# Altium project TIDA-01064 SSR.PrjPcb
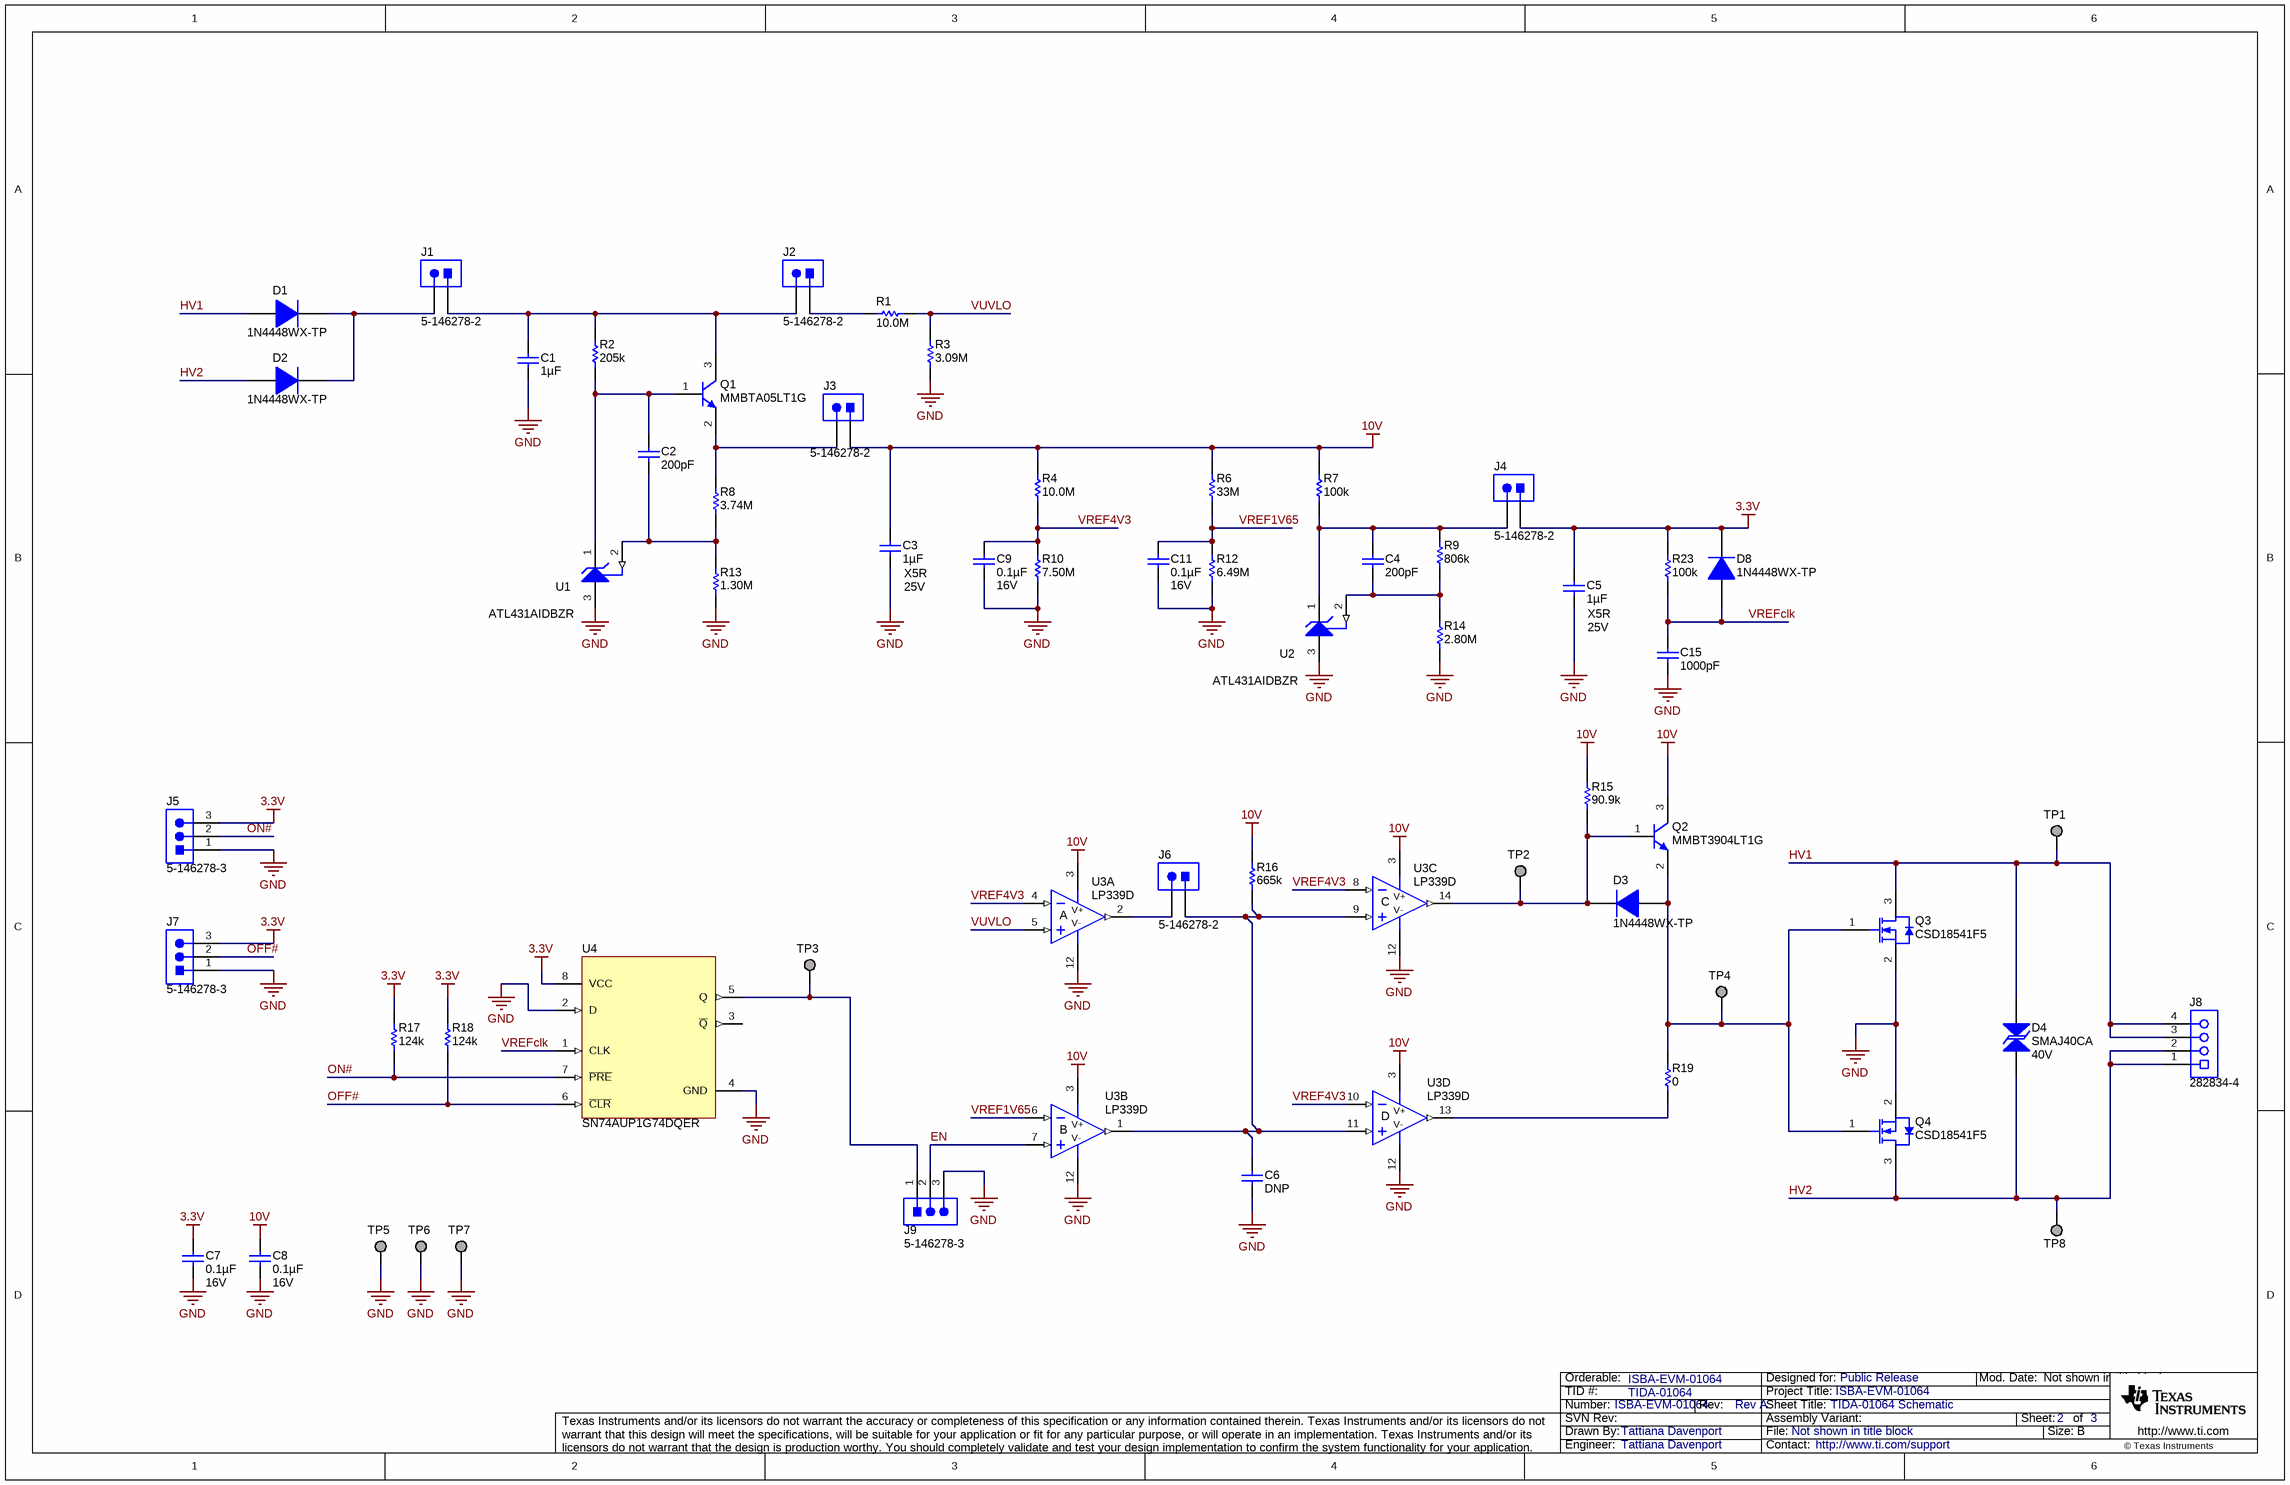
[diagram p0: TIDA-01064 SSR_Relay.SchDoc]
EVM_Orderable: ISBA-EVM-01064; PCB_Layout: Tattiana Davenport; PCB_Rev: Rev A; PRJ_Customer: Public Release; PRJ_Engineer: Tattiana Davenport; PRJ_Number: ISBA-EVM-01064; PRJ_Title: ISBA-EVM-01064; SCH_Rev: Rev A; TechSupport: http://www.ti.com/support; TID: TIDA-01064
3 sheets, 83 parts. Net scope: global (net labels, ports and power ports of the same name join across sheets).
Board file: TIDA-01064 SSR.PcbDoc
Sheets:
  TIDA-01064 SSR_Relay.SchDoc
  TIDA-01064 SSR_TID_Hardware.SchDoc
  TIDA-01064 SSR_CoverSheet.SchDoc

## Sheet TIDA-01064 SSR_Relay.SchDoc: TIDA-01064 Schematic
size 431 x 279 mm; Date: Not shown in title block; ApprovedBy: Not shown in title block; CheckedBy: Not shown in title block; Author: Not shown in title block; CompanyName: Not shown in title block; DrawnBy: Tattiana Davenport; Engineer: Not shown in title block; Organization: Not shown in title block; Address1: Not shown in title block; Address2: Not shown in title block; Address3: Not shown in title block; Address4: Not shown in title block; DocumentNumber: 1; Revision: Use project parameter SCH_Rev; SheetNumber: 2; SheetTotal: 3; PageSetup: Record=PageOptions¦CenterHorizontal=True¦CenterVertical=True¦PrintScale=0.62¦XCorrection=1.00¦YCorrection=1.00¦PrintKind=0¦BorderSize=5000000¦LeftOffset=0¦BottomOffset=0¦Orientation=2¦PaperLength=1000¦PaperWidth=1000¦Scale=100¦PaperSource=15¦PrintQuality=-3¦MediaType=1¦DitherType=10¦PrintScaleMode=1¦PaperKind=Letter¦PaperIndex=1

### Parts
C1  ValueDisplayed: 1µF  [1206_180]  (hidden comment: CL31B105KCHNNNE)
C2  ValueDisplayed: 200pF  [0603]  (hidden comment: GRM1885C1H201JA01D)
C3  ValueDisplayed: 1µF  Value2: 25V  TempCo: X5R  [0603]  (hidden comment: GRM188R61E105KA12D)
C4  ValueDisplayed: 200pF  [0603]  (hidden comment: GRM1885C1H201JA01D)
C5  ValueDisplayed: 1µF  Value2: 25V  TempCo: X5R  [0603]  (hidden comment: GRM188R61E105KA12D)
C6  ValueDisplayed: DNP  [0603]  (hidden comment: GRM188R61E105KA12D)
C7  ValueDisplayed: 0.1µF  Value2: 16V  [0603]  (hidden comment: GRM188R71C104KA01D)
C8  ValueDisplayed: 0.1µF  Value2: 16V  [0603]  (hidden comment: GRM188R71C104KA01D)
C9  ValueDisplayed: 0.1µF  Value2: 16V  [0603]  (hidden comment: GRM188R71C104KA01D)
C11  ValueDisplayed: 0.1µF  Value2: 16V  [0603]  (hidden comment: GRM188R71C104KA01D)
C15  ValueDisplayed: 1000pF  [0603]  (hidden comment: GRM188R71E102KA01D)
D1  1N4448WX-TP  [sod-323]
D2  1N4448WX-TP  [sod-323]
D3  1N4448WX-TP  [sod-323]
D4  SMAJ40CA  value 40V  [SMA]
D8  1N4448WX-TP  [sod-323]
J1  5-146278-2  [TE_5-146278-2]
J2  5-146278-2  [TE_5-146278-2]
J3  5-146278-2  [TE_5-146278-2]
J4  5-146278-2  [TE_5-146278-2]
J5  5-146278-3  [TE_5-146278-3]
J6  5-146278-2  [TE_5-146278-2]
J7  5-146278-3  [TE_5-146278-3]
J8  282834-4  [TEC_282834-4]
J9  5-146278-3  [TE_5-146278-3]
Q1  MMBTA05LT1G  [SOT-23]
Q2  MMBT3904LT1G  [SOT-23]
Q3  CSD18541F5  [YJK0003A]
Q4  CSD18541F5  [YJK0003A]
R1  ValueDisplayed: 10.0M  [0805_HV]  (hidden comment: CRCW080510M0FKEA)
R2  ValueDisplayed: 205k  [0805_HV]  (hidden comment: CRCW0805205KFKEA)
R3  ValueDisplayed: 3.09M  [0805_HV]  (hidden comment: CRCW08053M09FKEA)
R4  ValueDisplayed: 10.0M  [0805_HV]  (hidden comment: CRCW080510M0FKEA)
R6  ValueDisplayed: 33M  [0805_HV]  (hidden comment: RC0805JR-0733ML)
R7  ValueDisplayed: 100k  [0805_HV]  (hidden comment: CRCW0805100KFKEA)
R8  ValueDisplayed: 3.74M  [0805_HV]  (hidden comment: CRCW08053M74FKEA)
R9  ValueDisplayed: 806k  [0805_HV]  (hidden comment: CRCW0805806KFKEA)
R10  ValueDisplayed: 7.50M  [0805_HV]  (hidden comment: CRCW08057M50FKEA)
R12  ValueDisplayed: 6.49M  [0805_HV]  (hidden comment: CRCW08056M49FKEA)
R13  ValueDisplayed: 1.30M  [0805_HV]  (hidden comment: CRCW08051M30FKEA)
R14  ValueDisplayed: 2.80M  [0805_HV]  (hidden comment: CRCW08052M80FKEA)
R15  ValueDisplayed: 90.9k  [0805_HV]  (hidden comment: CRCW080590K9FKEA)
R16  ValueDisplayed: 665k  [0805_HV]  (hidden comment: CRCW0805665KFKEA)
R17  ValueDisplayed: 124k  [0805_HV]  (hidden comment: CRCW0805124KFKEA)
R18  ValueDisplayed: 124k  [0805_HV]  (hidden comment: CRCW0805124KFKEA)
R19  ValueDisplayed: 0  [0805_HV]  (hidden comment: CRCW08050000Z0EA)
R23  ValueDisplayed: 100k  [0805_HV]  (hidden comment: CRCW0805100KFKEA)
TP1  TESTPOINT  [Keystone_5019]  (value not drawn)  (no BOM)
TP2  TESTPOINT  [Keystone_5019]  (value not drawn)  (no BOM)
TP3  TESTPOINT  [Keystone_5019]  (value not drawn)  (no BOM)
TP4  TESTPOINT  [Keystone_5019]  (value not drawn)  (no BOM)
TP5  TESTPOINT  [Keystone_5019]  (value not drawn)  (no BOM)
TP6  TESTPOINT  [Keystone_5019]  (value not drawn)  (no BOM)
TP7  TESTPOINT  [Keystone_5019]  (value not drawn)  (no BOM)
TP8  TESTPOINT  [Keystone_5019]  (value not drawn)  (no BOM)
U1  ATL431AIDBZR  [DBZ0003A_M]
U2  ATL431AIDBZR  [DBZ0003A_M]
U3  LP339D  [D0014A_N]  (parts A,B,C,D of 4)
U4  SN74AUP1G74DQER  [DQE0008A]

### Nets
3.3V: C5.1 C7.2 D8.1(K) J4.1 J5.3 J7.3 R17.2 R18.2 R23.1 U4.8(VCC)
10V: C3.1 C8.2 J3.1 Q2.3(C) R4.2 R6.2 R7.2 R15.2 R16.2 U3.3(V+)
GND: C1.2 C3.2 C5.2 C6.2 C7.1 C8.1 C9.1 C11.1 C15.2 J5.1 J7.1 J9.3 Q3.2(S) Q4.2(S) R3.1 R10.1 R12.1 R13.1 R14.1 TP5.1 TP6.1 TP7.1 U1.3(ANODE) U2.3(ANODE) U3.12(V-) U4.2(D) U4.4(GND)
EN: J9.2 U3.7(+IN2)
HV1: D1.2(A) D4.2 J8.3 J8.4 Q3.3(D) TP1.1
HV2: D2.2(A) D4.1 J8.1 J8.2 Q4.3(D) TP8.1
OFF#: J7.2 R18.1 U4.6(~{CLR})
ON#: J5.2 R17.1 U4.7(~{PRE})
VREF1V65: C11.2 R6.1 R12.2 U3.6(-IN2)
VREF4V3: C9.2 R4.1 R10.2 U3.4(-IN1) U3.8(-IN3) U3.10(-IN4)
VREFclk: C15.1 D8.2(A) R23.2 U4.1(CLK)
VUVLO: R1.2 R3.2 U3.5(+IN1)
NetC1_1: C1.1 J1.1 J2.2 Q1.3(C) R2.2
NetC2_1: C2.1 Q1.1(B) R2.1 U1.1(CATHODE)
NetC2_2: C2.2 R8.1 R13.2 U1.2(REF)
NetC4_1: C4.1 J4.2 R7.1 R9.2 U2.1(CATHODE)
NetC4_2: C4.2 R9.1 R14.2 U2.2(REF)
NetC6_1: C6.1 J6.1 R16.1 U3.1(OUT2) U3.9(+IN3) U3.11(+IN4)
NetD1_1: D1.1(K) D2.1(K) J1.2
NetD3_1: D3.1(K) Q2.1(B) R15.1 TP2.1 U3.14(OUT3)
NetD3_2: D3.2(A) Q2.2(E) Q3.1(G) Q4.1(G) R19.2 TP4.1
NetJ2_1: J2.1 R1.1
NetJ3_2: J3.2 Q1.2(E) R8.2
NetJ6_2: J6.2 U3.2(OUT1)
NetJ9_1: J9.1 TP3.1 U4.5(Q)
NetR19_1: R19.1 U3.13(OUT4)

Not connected (* = marked no-connect by the designer): U4 3(~{Q})

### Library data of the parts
C1 = CL31B105KCHNNNE: CAP, CERM, 1 µF, 100 V, +/- 10%, X7R, 1206; Manufacturer: Samsung; Polarized: N; CompType: Capacitor; Value: 1uF; U/M: EA; Cap_F: 0.000001; Tolerance_%: 10; Value1: Unknown; VDC_V: 100; Value2: 100V; TaMin_C: -55; TaMax_C: 125; Cap_Case: 1206; AEC Category: Q200; SizeArea_mm2: 5.12; SizeAreaWB_mm2: 10.92; SizeX_mm: 3.2; SizeY_mm: 1.6; SizeZ_mm: 1.8
C2 C4 = GRM1885C1H201JA01D: CAP, CERM, 200 pF, 50 V, +/- 5%, C0G/NP0, 0603; Manufacturer: MuRata; Polarized: N; CompType: Capacitor; Value: 200pF; U/M: EA; Cap_F: 0.0000000002; Tolerance_%: 5; Value1: Unknown; VDC_V: 50; Value2: 50V; TaMin_C: -55; TaMax_C: 125; AEC Category: Q200
C3 C5 = GRM188R61E105KA12D: CAP, CERM, 1 µF, 25 V, +/- 10%, X5R, 0603; Manufacturer: MuRata; Polarized: N; CompType: Capacitor; Value: 1uF; U/M: EA; Cap_F: 0.000001; Tolerance_%: 10; Value1: Unknown; VDC_V: 25; TaMin_C: -55; TaMax_C: 85; AEC Category: Q200
C6 = GRM188R61E105KA12D: CAP, CERM, 1 µF, 25 V, +/- 10%, X5R, 0603; Manufacturer: MuRata; Polarized: N; CompType: Capacitor; Value: 1uF; U/M: EA; Cap_F: 0.000001; Tolerance_%: 10; Value1: Unknown; VDC_V: 25; Value2: 25V; TaMin_C: -55; TaMax_C: 85; AEC Category: Q200
C7-C9 C11 = GRM188R71C104KA01D: CAP, CERM, 0.1 µF, 16 V, +/- 10%, X7R, 0603; Manufacturer: MuRata; Polarized: N; CompType: Capacitor; Value: 0.1uF; U/M: EA; Cap_F: 0.0000001; Tolerance_%: 10; Value1: Unknown; VDC_V: 16; TaMin_C: -55; TaMax_C: 125; AEC Category: Q200
C15 = GRM188R71E102KA01D: CAP, CERM, 1000 pF, 25 V, +/- 10%, X7R, 0603; Manufacturer: MuRata; Polarized: N; CompType: Capacitor; Value: 1000pF; U/M: EA; Cap_F: 0.000000001; Tolerance_%: 10; Value1: Unknown; VDC_V: 25; Value2: 25V; TaMin_C: -55; TaMax_C: 125; SizeArea_mm2: 1.28; SizeAreaWB_mm2: 4.68; SizeX_mm: 1.6; SizeY_mm: 0.8; SizeZ_mm: 1; AEC Category: Q200
D1-D3 D8 = 1N4448WX-TP: Diode, Switching, 75 V, 0.25 A, SOD-323; Manufacturer: Micro Commercial Components; U/M: EA; Value: 75V; Value1: 0.25A; Io_A: 0.25; Vr_V: 75; TJmax_C: 150; AEC Category: Q101
D4 = SMAJ40CA: Diode, TVS, Bi, 40 V, 400 W, SMA; Manufacturer: Littelfuse; U/M: EA; Power_W: 400; Vr_V: 40; Value1: 400W; RJA_CperW: 120; AEC Category: Q101
J1-J4 J6 = 5-146278-2: Header, 100mil, 2x1, Tin, TH; Manufacturer: TE Connectivity; SymbolCreator: a0412235; U/M: EA
J5 J7 J9 = 5-146278-3: Header, 100mil, 3x1, Tin, TH; Manufacturer: TE Connectivity; SymbolCreator: a0799628
J8 = 282834-4: Terminal Block, 100mil, 4X1 TH; Manufacturer: TE Connectivity; SymbolCreator: a0411947
Q1 = MMBTA05LT1G, ON Semiconductor: Transistor, NPN, 60 V, 0.5 A, AEC-Q101, SOT-23; CompType: BJT; PNP: 0; NPN: 1; Vceo_V: 60; Vcesat1_V: 0.25; Value: 60 V; IcRated_A: 0.5; Value1: 0.5 A; TaMin_C: -55; TaMax_C: 150; U/M: EA; AEC Category: Q101; AEC Qualified: Y
Q2 = MMBT3904LT1G, ON Semiconductor: Transistor, NPN, 40 V, 0.2 A, SOT-23; CompType: BJT; PNP: 0; NPN: 1; Vceo_V: 40; Vcesat1_V: 0.3; Value: 40 V; IcRated_A: 0.2; Value1: 0.2 A; HfeMax: 300; TaMin_C: -55; TaMax_C: 150; U/M: EA; AEC Category: Q101
Q3 Q4 = CSD18541F5: MOSFET, N-CH, 60 V,  A, PICOSTAR-3; Manufacturer: Texas Instruments; Alternate Manufacturer: None; U/M: EA; ChType: N; Value: 60V; VdsMax_V: 60; Value1: 0.13 ohm; Rdson45_ohm: 0.13; Value2: 9.2 nC; QgTyp_nC: 9.2; Vgs_V: 20; AEC Category: Q101
R1 R4 = CRCW080510M0FKEA: RES, 10.0 M, 1%, 0.125 W, 0805; Manufacturer: Vishay-Dale; CompType: Resistor; Value: 10.0Meg; Res_ohm: 10000000; Value_Code: 10M0; Tolerance_%: 1; Power_W: 0.125; Value2: 0.125W; VDC_V: 150; TempCo: 100 ppm/C; EIA_Code: E96; U/M: EA; AEC Category: Q200
R2 = CRCW0805205KFKEA: RES, 205 k, 1%, 0.125 W, 0805; Manufacturer: Vishay-Dale; CompType: Resistor; Value: 205k; Res_ohm: 205000; Tolerance_%: 1; Power_W: 0.125; Value2: 0.125W; VDC_V: 150; TempCo: 100 ppm/C; EIA_Code: E96; U/M: EA; AEC Category: Q200
R3 = CRCW08053M09FKEA: RES, 3.09 M, 1%, 0.125 W, 0805; Manufacturer: Vishay-Dale; CompType: Resistor; Value: 3.09Meg; Res_ohm: 3090000; Value_Code: 3M09; Tolerance_%: 1; Power_W: 0.125; Value2: 0.125W; VDC_V: 150; TempCo: 100 ppm/C; EIA_Code: E96; U/M: EA; AEC Category: Q200
R6 = RC0805JR-0733ML: RES, 33 M, 5%, 0.125 W, 0805; Manufacturer: Yageo America; CompType: Resistor; Value: 33Meg; Res_ohm: 33000000; Value_Code: 33M0; Tolerance_%: 5; Power_W: 0.125; Value2: 0.125W; VDC_V: 150; TempCo: 300 ppm/C; U/M: EA; AEC Category: Q200; AEC Qualified: N
R7 R23 = CRCW0805100KFKEA: RES, 100 k, 1%, 0.125 W, 0805; Manufacturer: Vishay-Dale; CompType: Resistor; Value: 100k; Res_ohm: 100000; Tolerance_%: 1; Power_W: 0.125; Value2: 0.125W; VDC_V: 150; TempCo: 100 ppm/C; EIA_Code: E96; U/M: EA; AEC Category: Q200
R8 = CRCW08053M74FKEA: RES, 3.74 M, 1%, 0.125 W, 0805; Manufacturer: Vishay-Dale; CompType: Resistor; Value: 3.74Meg; Res_ohm: 3740000; Value_Code: 3M74; Tolerance_%: 1; Power_W: 0.125; Value2: 0.125W; VDC_V: 150; TempCo: 100 ppm/C; EIA_Code: E96; U/M: EA; AEC Category: Q200
R9 = CRCW0805806KFKEA: RES, 806 k, 1%, 0.125 W, 0805; Manufacturer: Vishay-Dale; CompType: Resistor; Value: 806k; Res_ohm: 806000; Tolerance_%: 1; Power_W: 0.125; Value2: 0.125W; VDC_V: 150; TempCo: 100 ppm/C; EIA_Code: E96; U/M: EA; AEC Category: Q200
R10 = CRCW08057M50FKEA: RES, 7.50 M, 1%, 0.125 W, 0805; Manufacturer: Vishay-Dale; CompType: Resistor; Value: 7.50Meg; Res_ohm: 7500000; Value_Code: 7M50; Tolerance_%: 1; Power_W: 0.125; Value2: 0.125W; VDC_V: 150; TempCo: 100 ppm/C; EIA_Code: E96; U/M: EA; AEC Category: Q200
R12 = CRCW08056M49FKEA: RES, 6.49 M, 1%, 0.125 W, 0805; Manufacturer: Vishay-Dale; CompType: Resistor; Value: 6.49Meg; Res_ohm: 6490000; Value_Code: 6M49; Tolerance_%: 1; Power_W: 0.125; Value2: 0.125W; VDC_V: 150; TempCo: 100 ppm/C; EIA_Code: E96; U/M: EA; AEC Category: Q200
R13 = CRCW08051M30FKEA: RES, 1.30 M, 1%, 0.125 W, 0805; Manufacturer: Vishay-Dale; CompType: Resistor; Value: 1.30Meg; Res_ohm: 1300000; Value_Code: 1M30; Tolerance_%: 1; Power_W: 0.125; Value2: 0.125W; VDC_V: 150; TempCo: 100 ppm/C; EIA_Code: E96; U/M: EA; AEC Category: Q200
R14 = CRCW08052M80FKEA: RES, 2.80 M, 1%, 0.125 W, 0805; Manufacturer: Vishay-Dale; CompType: Resistor; Value: 2.80Meg; Res_ohm: 2800000; Value_Code: 2M80; Tolerance_%: 1; Power_W: 0.125; Value2: 0.125W; VDC_V: 150; TempCo: 100 ppm/C; EIA_Code: E96; U/M: EA; AEC Category: Q200
R15 = CRCW080590K9FKEA: RES, 90.9 k, 1%, 0.125 W, 0805; Manufacturer: Vishay-Dale; CompType: Resistor; Value: 90.9k; Res_ohm: 90900; Value_Code: 90k9; Tolerance_%: 1; Power_W: 0.125; Value2: 0.125W; VDC_V: 150; TempCo: 100 ppm/C; EIA_Code: E96; U/M: EA; AEC Category: Q200
R16 = CRCW0805665KFKEA: RES, 665 k, 1%, 0.125 W, 0805; Manufacturer: Vishay-Dale; CompType: Resistor; Value: 665k; Res_ohm: 665000; Tolerance_%: 1; Power_W: 0.125; Value2: 0.125W; VDC_V: 150; TempCo: 100 ppm/C; EIA_Code: E96; U/M: EA; AEC Category: Q200; SizeArea_mm2: 2.5; SizeX_mm: 2; SizeY_mm: 1.25; SizeZ_mm: 1.45
R17 R18 = CRCW0805124KFKEA: RES, 124 k, 1%, 0.125 W, 0805; Manufacturer: Vishay-Dale; CompType: Resistor; Value: 124k; Res_ohm: 124000; Tolerance_%: 1; Power_W: 0.125; Value2: 0.125W; VDC_V: 150; TempCo: 100 ppm/C; EIA_Code: E96; U/M: EA; AEC Category: Q200
R19 = CRCW08050000Z0EA: RES, 0, 5%, 0.125 W, 0805; Manufacturer: Vishay-Dale; CompType: Resistor; Value: 0; Value_Code: 0000; Tolerance_%: 5; Power_W: 0.125; Value2: 0.125W; VDC_V: 150; TempCo: 200 ppm/C; EIA_Code: E24; U/M: EA; AEC Category: Q200
TP1-TP8 = 5019: Test Point, Miniature, SMT; Manufacturer: Keystone; CompType: Test Point Loop
U1 U2 = ATL431AIDBZR: 2.5V Low Iq Adjustable Precision Shunt Regulator, DBZ0003A; Manufacturer: Texas Instruments; SymbolCreator: a0412235; CompType: IC; U/M: EA
U3 = LP339D: Quad, Low-Power, General Purpose Differential Comparator, D0014A; Manufacturer: Texas Instruments; SymbolCreator: Altium; CompType: OpAmp IC
U4 = SN74AUP1G74DQER: LOW-POWER SINGLE POSITIVE-EDGE-TRIGGERED D-TYPE FLIP-FLOP WITH CLEAR AND PRESET, DQE0008A; Manufacturer: Texas Instruments; SymbolCreator: a0799628; CompType: IC; U/M: EA

## Sheet TIDA-01064 SSR_TID_Hardware.SchDoc: Hardware
size 431 x 279 mm; Date: Not shown in title block; ApprovedBy: Not shown in title block; CheckedBy: Not shown in title block; Author: Not shown in title block; CompanyName: Not shown in title block; DrawnBy: Tattiana Davenport; Engineer: Not shown in title block; Organization: Not shown in title block; Address1: Not shown in title block; Address2: Not shown in title block; Address3: Not shown in title block; Address4: Not shown in title block; DocumentNumber: 1; Revision: Use project parameter SCH_Rev; SheetNumber: 3; SheetTotal: 3; PageSetup: Record=PageOptions¦CenterHorizontal=True¦CenterVertical=True¦PrintScale=1.00¦XCorrection=1.00¦YCorrection=1.00¦PrintKind=0¦BorderSize=5000000¦LeftOffset=0¦BottomOffset=0¦Orientation=2¦PaperLength=1000¦PaperWidth=1000¦Scale=100¦PaperSource=15¦PrintQuality=600¦MediaType=1¦DitherType=10¦PaperKind=Letter¦PrintScaleMode=1
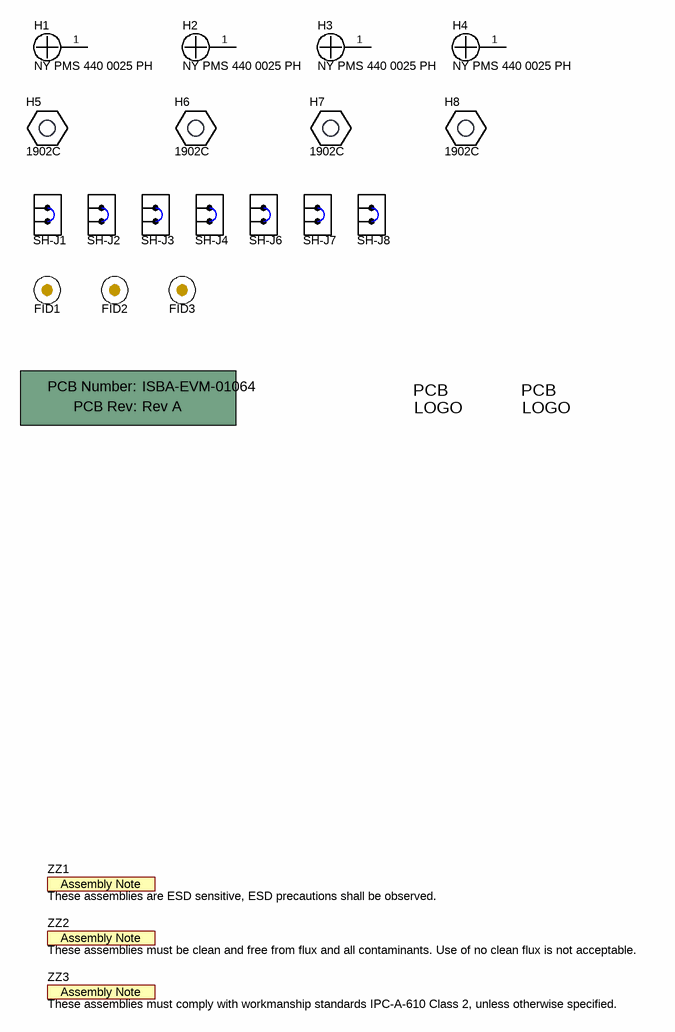
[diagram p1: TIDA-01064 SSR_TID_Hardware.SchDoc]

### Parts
!PCB1  Printed Circuit Board  (value not drawn)  (mechanical)
FCC_Disclaimer  FCC disclaimer  [FCC_disclaimer]  (value not drawn)  (no BOM)
FID1  Fiducial  [Fiducial10-20]  (value not drawn)
FID2  Fiducial  [Fiducial10-20]  (value not drawn)
FID3  Fiducial  [Fiducial10-20]  (value not drawn)
H1  NY PMS 440 0025 PH  [NY PMS 440 0025 PH]
H2  NY PMS 440 0025 PH  [NY PMS 440 0025 PH]
H3  NY PMS 440 0025 PH  [NY PMS 440 0025 PH]
H4  NY PMS 440 0025 PH  [NY PMS 440 0025 PH]
H5  1902C  [Keystone_1902C]
H6  1902C  [Keystone_1902C]
H7  1902C  [Keystone_1902C]
H8  1902C  [Keystone_1902C]
Logo?  Pb-Free Symbol  [Pb-Free_Overlay_Medium]  (value not drawn)  (no BOM)
SH-J1  SPC02SYAN  [SPC02SYAN]  (value not drawn)
SH-J2  SPC02SYAN  [SPC02SYAN]  (value not drawn)
SH-J3  SPC02SYAN  [SPC02SYAN]  (value not drawn)
SH-J4  SPC02SYAN  [SPC02SYAN]  (value not drawn)
SH-J6  SPC02SYAN  [SPC02SYAN]  (value not drawn)
SH-J7  SPC02SYAN  [SPC02SYAN]  (value not drawn)
SH-J8  SPC02SYAN  [SPC02SYAN]  (value not drawn)
ZZ1  These assemblies are ESD sensitive, ESD precautions shall be observed.  [AssemblyNote]  (no BOM)
ZZ2  These assemblies must be clean and free from flux and all contaminants. Use of no clean flux is not acceptable.  [AssemblyNote]  (no BOM)
ZZ3  These assemblies must comply with workmanship standards IPC-A-610 Class 2, unless otherwise specified.  [AssemblyNote]  (no BOM)

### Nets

Not connected (* = marked no-connect by the designer): H1 1; H2 1; H3 1; H4 1

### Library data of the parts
!PCB1 = PCB: Manufacturer: Any; PartNumber: ISBA-EVM-01064; SymbolCreator: a0412235
FCC_Disclaimer = FCC_disclaimer: SymbolCreator: a0412235
FID1-FID3 = Fiducial: Fiducial mark.  There is nothing to buy or mount.; SymbolCreator: codlsc
H1-H4 = NY PMS 440 0025 PH: Machine Screw, Round, #4-40 x 1/4, Nylon, Philips panhead; Manufacturer: B&F Fastener Supply; CompType: Hardware; SymbolCreator: codlsc; U/M: EA
H5-H8 = 1902C: Standoff, Hex, 0.5"L #4-40 Nylon; Manufacturer: Keystone; CompType: Hardware
Logo? = Pb-Free: SymbolCreator: a0412235
SH-J1-SH-J4 SH-J6-SH-J8 = SPC02SYAN: Shunt, 100mil, Flash Gold, Black; Manufacturer: Sullins Connector Solutions; Value: 1x2; Note: You can "mate" this to a header by matching the designator.  i.e. use SH-J3 for header J3
ZZ1-ZZ3 = AssemblyNote: SymbolCreator: codlsc

## Sheet TIDA-01064 SSR_CoverSheet.SchDoc: CoverSheet
size 431 x 279 mm; Date: Not shown in title block; ApprovedBy: Not shown in title block; CheckedBy: Not shown in title block; Author: Not shown in title block; CompanyName: Not shown in title block; DrawnBy: Tattiana Davenport; Engineer: Not shown in title block; Organization: Not shown in title block; Address1: Not shown in title block; Address2: Not shown in title block; Address3: Not shown in title block; Address4: Not shown in title block; DocumentNumber: 1; Revision: Use project parameter SCH_Rev; SheetNumber: 1; SheetTotal: 3; PageSetup: Record=PageOptions¦CenterHorizontal=True¦CenterVertical=True¦PrintScale=1.00¦XCorrection=1.00¦YCorrection=1.00¦PrintKind=0¦BorderSize=5000000¦LeftOffset=0¦BottomOffset=0¦Orientation=2¦PaperLength=1000¦PaperWidth=1000¦Scale=100¦PaperSource=15¦PrintQuality=600¦MediaType=1¦DitherType=10¦PaperKind=Letter¦PrintScaleMode=1
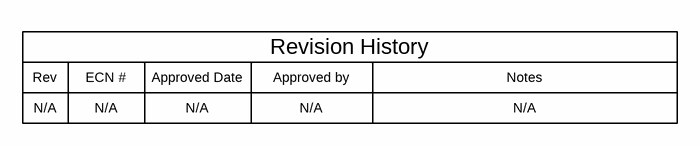
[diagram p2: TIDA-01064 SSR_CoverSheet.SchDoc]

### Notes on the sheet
- Rev
- N/A
- ECN #
- Approved Date
- Approved by
- Revision History
- Notes

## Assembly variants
001: not fitted !PCB1 C6 FID1 FID2 FID3 H1 H2 H3 H4 H5 H6 H7 H8 SH-J1 SH-J2 SH-J3 SH-J4 SH-J6 SH-J7 SH-J8 ZZ1 ZZ2 ZZ3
